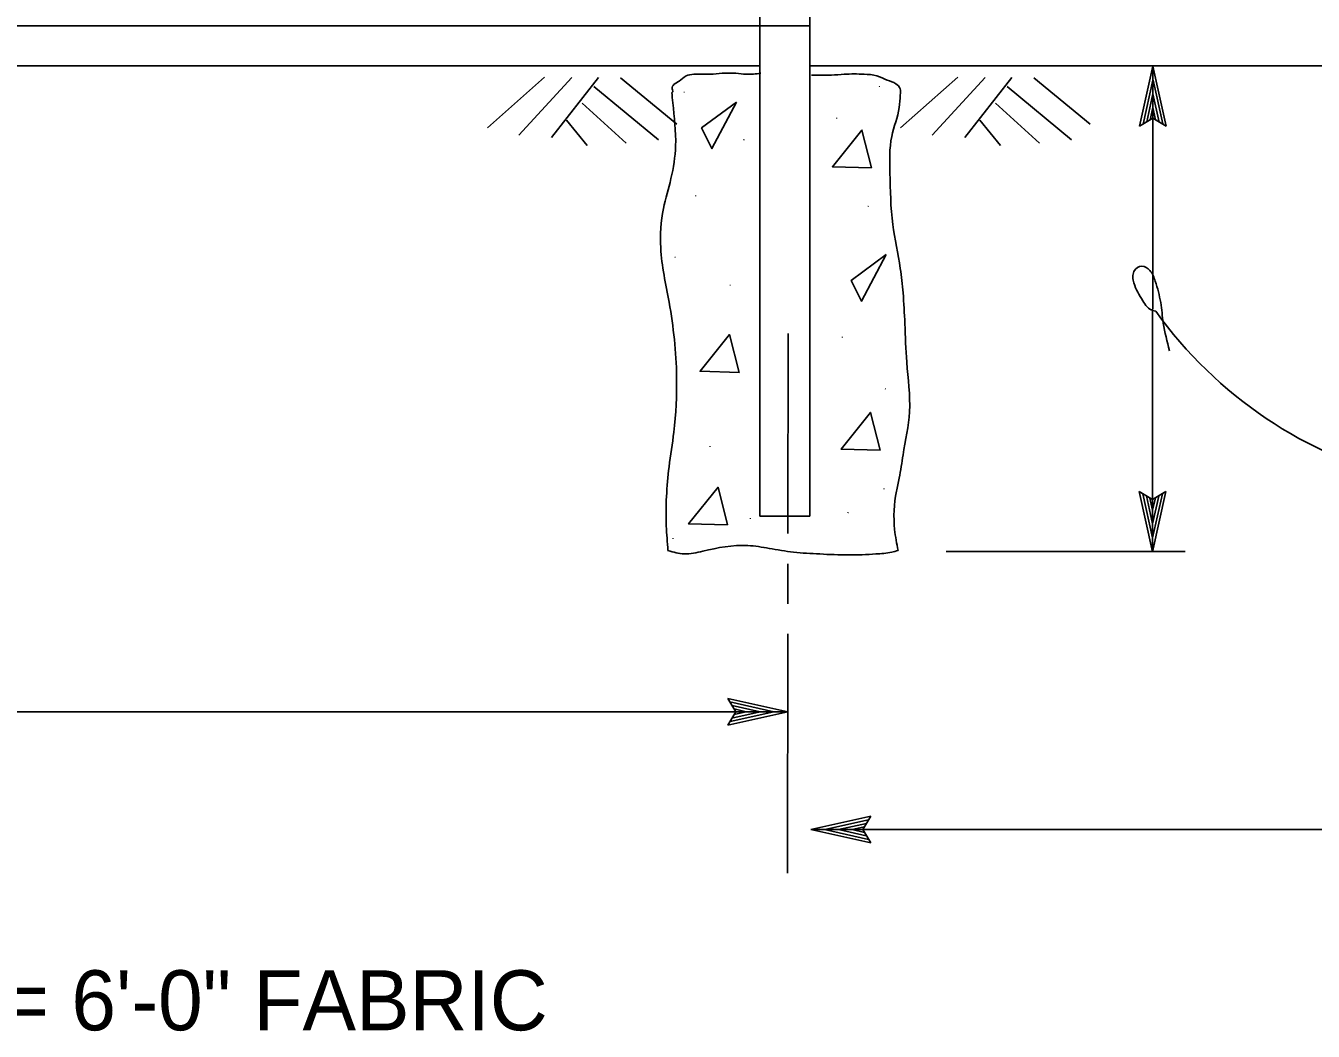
# Model space of a CAD drawing. Extents: x -121875 to -117742, y -103854 to -101122.
# Drawn here: x -121240.4 to -121111.6, y -102477.7 to -102377.2 of the extents above; entities that cross this region are included whole.
import ezdxf

# ---------------------------------------------------------------- set-up
doc = ezdxf.new("R2010")
doc.units = 0
for name, color, linetype in [('G-MARK', 7, 'Continuous'), ('G-TEXT', 7, 'Continuous'), ('Misc CnstDet(22)', 7, 'Continuous'), ('Nongeo Data(60)', 7, 'Continuous')]:
    doc.layers.add(name, color=color, linetype=linetype)

msp = doc.modelspace()

# ---------------------------------------------------------------- linework, layer by layer
at = {"layer": 'G-MARK'}
for p, q in [((-121127.71, -102429.78), (-121127.67, -102381.27)), ((-121148.34, -102429.76), (-121124.46, -102429.76)), ((-121341.08, -102445.78), (-121164.19, -102445.78)), ((-121161.89, -102457.55), (-120749.46, -102457.55))]:
    msp.add_line(p, q, dxfattribs=at)
for points in [[(-121164.15, -102407.98), (-121164.17, -102427.98)], [(-121164.17, -102430.98), (-121164.17, -102434.98)], [(-121164.18, -102437.98), (-121164.2, -102461.92)]]:
    msp.add_lwpolyline(points, dxfattribs=at)
msp.add_arc((-121092.33, -102380.7), 43.08, 215.5482, 256.6593, dxfattribs=at)
msp.add_spline([(-121127.38, -102405.74), (-121127.7, -102405.69), (-121128.68, -102404.71), (-121129.57, -102402.93), (-121129.57, -102401.77), (-121128.77, -102401.24), (-121127.97, -102401.68), (-121127.44, -102402.75), (-121126.9, -102404.89), (-121126.64, -102406.94), (-121126.01, -102409.7)], degree=3, dxfattribs=at)
at = {"layer": 'G-TEXT'}
for p, q in [((-121129.01, -102387.27), (-121127.67, -102381.27)), ((-121127.67, -102381.27), (-121127.67, -102381.27)), ((-121127.67, -102381.27), (-121126.34, -102387.27)), ((-121128.66, -102387.05), (-121127.67, -102382.65)), ((-121127.66, -102382.66), (-121126.7, -102387.03)), ((-121128.3, -102386.82), (-121127.67, -102384.03)), ((-121127.67, -102384.03), (-121127.05, -102386.86)), ((-121127.95, -102386.64), (-121127.67, -102385.41)), ((-121127.67, -102385.41), (-121127.41, -102386.62)), ((-121127.67, -102386.47), (-121129.01, -102387.27)), ((-121129.01, -102387.27), (-121129.01, -102387.27)), ((-121126.34, -102387.27), (-121127.67, -102386.47)), ((-121126.34, -102387.27), (-121126.34, -102387.27)), ((-121127.71, -102429.78), (-121129.04, -102423.78)), ((-121129.04, -102423.78), (-121129.04, -102423.78)), ((-121129.04, -102423.78), (-121127.71, -102424.58)), ((-121127.72, -102428.39), (-121128.68, -102424.01)), ((-121127.71, -102427.01), (-121128.33, -102424.19)), ((-121127.71, -102425.63), (-121127.97, -102424.42)), ((-121127.71, -102424.58), (-121126.37, -102423.78)), ((-121126.37, -102423.78), (-121127.71, -102429.78)), ((-121126.72, -102423.99), (-121127.71, -102428.4)), ((-121127.08, -102424.23), (-121127.71, -102427.01)), ((-121127.43, -102424.4), (-121127.71, -102425.63)), ((-121126.37, -102423.78), (-121126.37, -102423.78)), ((-121127.71, -102429.78), (-121127.71, -102429.78)), ((-121169.39, -102445.78), (-121170.19, -102444.44)), ((-121170.19, -102444.44), (-121170.19, -102444.44)), ((-121170.19, -102444.44), (-121164.19, -102445.78)), ((-121169.97, -102444.8), (-121165.57, -102445.78)), ((-121169.74, -102445.16), (-121166.95, -102445.78)), ((-121169.56, -102445.5), (-121168.33, -102445.78)), ((-121164.19, -102445.78), (-121170.19, -102447.11)), ((-121170.19, -102447.11), (-121169.39, -102445.78)), ((-121165.58, -102445.78), (-121169.95, -102446.75)), ((-121166.95, -102445.78), (-121169.78, -102446.4)), ((-121168.33, -102445.78), (-121169.54, -102446.05)), ((-121164.19, -102445.78), (-121164.19, -102445.78)), ((-121170.19, -102447.11), (-121170.19, -102447.11)), ((-121161.89, -102457.55), (-121155.89, -102456.22)), ((-121160.49, -102457.55), (-121156.12, -102456.58)), ((-121159.12, -102457.55), (-121156.3, -102456.93)), ((-121155.89, -102456.22), (-121156.69, -102457.55)), ((-121155.89, -102456.22), (-121155.89, -102456.22)), ((-121155.89, -102458.89), (-121161.89, -102457.55)), ((-121161.89, -102457.55), (-121161.89, -102457.55)), ((-121156.1, -102458.53), (-121160.51, -102457.55)), ((-121156.34, -102458.17), (-121159.12, -102457.55)), ((-121157.74, -102457.55), (-121156.53, -102457.29)), ((-121156.51, -102457.83), (-121157.74, -102457.55)), ((-121156.69, -102457.55), (-121155.89, -102458.89)), ((-121155.89, -102458.89), (-121155.89, -102458.89))]:
    msp.add_line(p, q, dxfattribs=at)
at = {"layer": 'Nongeo Data(60)'}
for p, q in [((-121166.97, -102426.24), (-121166.97, -102366.89)), ((-121161.97, -102426.24), (-121161.97, -102366.89)), ((-121161.97, -102377.24), (-121337.33, -102377.24)), ((-121166.97, -102381.24), (-121338.97, -102381.24)), ((-120959.35, -102381.24), (-121161.97, -102381.24)), ((-121188.5, -102382.37), (-121194.21, -102387.44)), ((-121185.76, -102382.41), (-121191.06, -102388.16)), ((-121183.1, -102382.41), (-121187.8, -102388.39)), ((-121180.9, -102382.43), (-121175.27, -102387.07)), ((-121147.19, -102382.37), (-121152.9, -102387.44)), ((-121144.45, -102382.41), (-121149.75, -102388.16)), ((-121141.79, -102382.41), (-121146.49, -102388.39)), ((-121139.59, -102382.43), (-121133.96, -102387.07)), ((-121183.56, -102383.3), (-121177.12, -102388.61)), ((-121142.25, -102383.3), (-121135.81, -102388.61)), ((-121184.74, -102384.95), (-121180.34, -102388.96)), ((-121143.43, -102384.95), (-121139.03, -102388.96)), ((-121186.3, -102386.67), (-121184.24, -102389.2)), ((-121144.99, -102386.67), (-121142.93, -102389.2)), ((-121161.97, -102426.24), (-121166.97, -102426.24)), ((-121161.97, -102426.24), (-121166.97, -102426.24)), ((-121161.97, -102426.24), (-121166.97, -102426.24))]:
    msp.add_line(p, q, dxfattribs=at)
for points in [[(-121169.3, -102384.85), (-121171.77, -102389.5), (-121172.8, -102387.43)], [(-121155.82, -102391.43), (-121159.72, -102391.32), (-121156.77, -102387.66)], [(-121154.35, -102400.1), (-121156.82, -102404.75), (-121157.84, -102402.68)], [(-121169.05, -102411.86), (-121172.95, -102411.75), (-121170, -102408.09)], [(-121154.96, -102419.63), (-121158.86, -102419.52), (-121155.9, -102415.86)], [(-121170.2, -102427.11), (-121174.1, -102427), (-121171.15, -102423.34)]]:
    msp.add_lwpolyline(points, close=True, dxfattribs=at)
for points in [[(-121175.78, -102383.88), (-121175.73, -102383.88), (-121175.73, -102383.53), (-121175.56, -102383.1), (-121175.05, -102382.76), (-121174.36, -102382.24), (-121173.58, -102382.07), (-121171.95, -102382.07), (-121170.75, -102381.98), (-121169.37, -102381.98), (-121168.34, -102382.07), (-121166.88, -102381.98)], [(-121152.95, -102384.14), (-121152.94, -102383.53), (-121153.37, -102383.02), (-121154.23, -102382.67), (-121155.27, -102382.24), (-121156.56, -102382.07), (-121158.53, -102382.07), (-121159.82, -102382.16), (-121161.2, -102382.16), (-121161.8, -102382.16)], [(-121175.78, -102383.88), (-121175.68, -102384.92), (-121175.4, -102389.22), (-121175.86, -102392.5), (-121176.61, -102395.49), (-121176.89, -102399.42), (-121176.05, -102404.85), (-121175.3, -102412.33), (-121175.58, -102417.85), (-121176.05, -102421.31), (-121176.33, -102427.21), (-121176.16, -102429.66)], [(-121153.16, -102429.66), (-121153.5, -102427.58), (-121153.32, -102423.75), (-121153.04, -102422.44), (-121152.66, -102420.1), (-121152.01, -102415.79), (-121152.29, -102410.84), (-121152.48, -102407), (-121152.66, -102403.91), (-121152.94, -102401.48), (-121153.69, -102397.08), (-121153.97, -102391.94), (-121153.79, -102388.29), (-121153.04, -102385.39), (-121152.95, -102384.14)], [(-121176.16, -102429.66), (-121174.55, -102430.01), (-121172.68, -102429.73), (-121168.19, -102429.17), (-121166.04, -102429.45), (-121163.61, -102429.83), (-121160.99, -102430.01), (-121158.09, -102430.11), (-121155.38, -102430.01), (-121153.79, -102429.83), (-121153.16, -102429.66)]]:
    msp.add_spline(points, degree=3, dxfattribs=at)

# ---------------------------------------------------------------- texts
at = {"layer": 'Misc CnstDet(22)'}
msp.add_text('TYPE CL-6 = 6\'-0" FABRIC', height=6, dxfattribs=at).set_placement((-121285.53, -102477.61))
at = {"layer": 'Nongeo Data(60)'}
for p in [(-121174.6, -102383.72), (-121155.07, -102383.15), (-121159.36, -102386.31), (-121168.61, -102388.46), (-121173.45, -102394.08), (-121156.2, -102395.12), (-121175.5, -102400.2), (-121170, -102403), (-121158.79, -102408.18), (-121154.47, -102413.36), (-121172.02, -102419.11), (-121154.62, -102423.34), (-121158.21, -102425.73), (-121167.99, -102426.31), (-121175.72, -102428.3)]:
    msp.add_text('.', height=0.8, rotation=266.9315, dxfattribs=at).set_placement(p)

doc.saveas('drawing.dxf')
